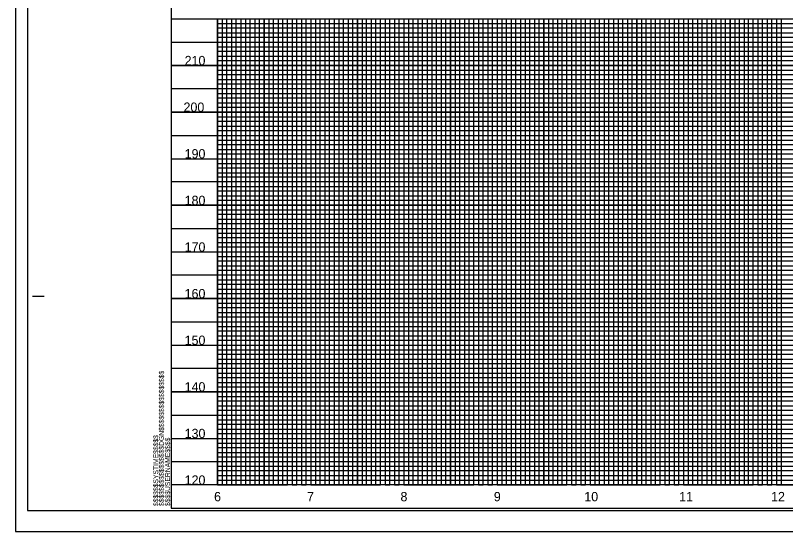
# Model space of a CAD drawing. Extents: x 1779926 to 1781610, y 620464 to 621564.
# Drawn here: x 1779926 to 1780753, y 620464 to 621018 of the extents above; entities that cross this region are included whole.
import ezdxf

# ---------------------------------------------------------------- set-up
doc = ezdxf.new("R2010")
doc.units = 0
for name, color, linetype in [('Exist Vertical Profile Horizontal Axis Label Major', 7, 'Continuous'), ('Exist Vertical Profile Vertical Axis Label', 7, 'Continuous'), ('Scratch_Level_0', 7, 'Continuous'), ('Sheet Cutting Line CELL', 7, 'Continuous'), ('Sheet DOT Grid CELL', 7, 'Continuous'), ('Sheet Layout Profile Border Port 2', 7, 'Continuous'), ('Sheet Plot Border Inside CELL', 7, 'Continuous'), ('Sheet Plot Border Outside CELL', 7, 'Continuous'), ('Sheet Profile CELL', 7, 'Continuous'), ('Sheet Profile Grid Major CELL', 7, 'Continuous'), ('Sheet Profile Grid Middle CELL', 7, 'Continuous'), ('Sheet Profile Grid Minor CELL', 7, 'Continuous')]:
    doc.layers.add(name, color=color, linetype=linetype)

msp = doc.modelspace()

# ---------------------------------------------------------------- linework, layer by layer
at = {"layer": 'Scratch_Level_0'}
msp.add_lwpolyline([(1780142.96, 620514.19), (1780142.96, 621014.19), (1781542.96, 621014.19), (1781542.96, 620514.19)], close=True, dxfattribs=at)
at = {"layer": 'Sheet Cutting Line CELL'}
for p, q in [((1779925.96, 621564.19), (1779925.96, 620464.19)), ((1779925.96, 620464.19), (1781609.96, 620464.19))]:
    msp.add_line(p, q, dxfattribs=at)
at = {"layer": 'Sheet DOT Grid CELL'}
for p, q in [((1780092.96, 621014.19), (1781592.85, 621014.19)), ((1780142.96, 621014.19), (1780142.96, 620514.19)), ((1780192.96, 621014.19), (1780192.96, 620514.19)), ((1780242.96, 621014.19), (1780242.96, 620514.19)), ((1780292.96, 621014.19), (1780292.96, 620514.19)), ((1780342.96, 621014.19), (1780342.96, 620514.19)), ((1780392.96, 621014.19), (1780392.96, 620514.19)), ((1780442.96, 621014.19), (1780442.96, 620514.19)), ((1780492.96, 621014.19), (1780492.96, 620514.19)), ((1780542.96, 621014.19), (1780542.96, 620514.19)), ((1780592.96, 621014.19), (1780592.96, 620514.19)), ((1780642.96, 621014.19), (1780642.96, 620514.19)), ((1780692.96, 621014.19), (1780692.96, 620514.19)), ((1780742.96, 621014.19), (1780742.96, 620514.19)), ((1780092.96, 620964.19), (1781592.85, 620964.19)), ((1780092.96, 620914.19), (1781592.85, 620914.19)), ((1780092.96, 620864.19), (1781592.85, 620864.19)), ((1780092.96, 620814.19), (1781592.85, 620814.19)), ((1780092.96, 620764.19), (1781592.85, 620764.19)), ((1780092.96, 620714.19), (1781592.85, 620714.19)), ((1780092.96, 620664.19), (1781592.85, 620664.19)), ((1780092.96, 620614.19), (1781592.85, 620614.19)), ((1780092.96, 620564.19), (1781592.85, 620564.19))]:
    msp.add_line(p, q, dxfattribs=at)
at = {"layer": 'Sheet Layout Profile Border Port 2'}
for points in [[(1780142.96, 621014.19), (1781542.96, 621014.19), (1781542.96, 620514.19), (1780142.96, 620514.19)], [(1780142.96, 621014.19), (1781382.96, 621014.19), (1781382.96, 620514.19), (1780142.96, 620514.19)]]:
    msp.add_lwpolyline(points, close=True, dxfattribs=at)
at = {"layer": 'Sheet Plot Border Inside CELL'}
msp.add_lwpolyline([(1779938.96, 620486.64), (1781605.46, 620486.64), (1781605.46, 621541.74), (1779938.96, 621541.74)], close=True, dxfattribs=at)
at = {"layer": 'Sheet Plot Border Outside CELL'}
msp.add_lwpolyline([(1779925.96, 620464.19), (1781609.96, 620464.19), (1781609.96, 621564.19), (1779925.96, 621564.19)], close=True, dxfattribs=at)
at = {"layer": 'Sheet Profile CELL'}
for p, q in [((1780092.96, 621014.19), (1781592.96, 621014.19)), ((1779944.46, 620716.69), (1779956.96, 620716.69)), ((1781592.96, 620514.19), (1780092.96, 620514.19)), ((1780092.96, 620489.19), (1781592.96, 620489.19)), ((1780092.96, 620489.19), (1780092.96, 620489.19)), ((1780092.96, 620489.19), (1780092.96, 620489.19)), ((1780092.96, 620489.19), (1780092.96, 620489.19)), ((1780092.96, 620489.19), (1780092.96, 620489.19)), ((1780092.96, 620489.19), (1780092.96, 620489.19)), ((1780092.96, 620489.19), (1780092.96, 620489.19)), ((1780092.96, 620489.19), (1780092.96, 620489.19))]:
    msp.add_line(p, q, dxfattribs=at)
msp.add_lwpolyline([(1781592.96, 621539.19), (1780092.96, 621539.19), (1780092.96, 620489.19), (1781592.96, 620489.19)], close=True, dxfattribs=at)
msp.add_lwpolyline([(1780130.46, 620489.19), (1780130.46, 620489.19)], dxfattribs=at)
at = {"layer": 'Sheet Profile Grid Major CELL'}
for p, q in [((1780592.96, 621014.19), (1780642.96, 621014.19)), ((1780692.96, 621014.19), (1780742.96, 621014.19)), ((1780092.96, 620514.19), (1780092.96, 620514.19))]:
    msp.add_line(p, q, dxfattribs=at)
for points in [[(1780142.96, 621014.19), (1780142.96, 620514.19), (1780192.96, 620514.19), (1780192.96, 621014.19), (1780242.96, 621014.19), (1780242.96, 620514.19), (1780292.96, 620514.19), (1780292.96, 621014.19), (1780342.96, 621014.19), (1780342.96, 620514.19), (1780392.96, 620514.19), (1780392.96, 621014.19), (1780442.96, 621014.19), (1780442.96, 620514.19), (1780492.96, 620514.19), (1780492.96, 621014.19), (1780542.96, 621014.19), (1780542.96, 620514.19), (1780592.96, 620514.19), (1780592.96, 621014.19), (1780642.96, 621014.19), (1780642.96, 620514.19), (1780692.96, 620514.19), (1780692.96, 621014.19), (1780742.96, 621014.19), (1780742.96, 620514.19), (1780792.96, 620514.19)], [(1781592.96, 620964.19), (1780092.96, 620964.19)], [(1781592.96, 620914.19), (1780092.96, 620914.19), (1780092.96, 620864.19), (1781592.96, 620864.19)], [(1781592.96, 620814.19), (1780092.96, 620814.19), (1780092.96, 620764.19), (1781592.96, 620764.19)], [(1781592.96, 620714.19), (1780092.96, 620714.19), (1780092.96, 620664.19), (1781592.96, 620664.19)], [(1781592.96, 620614.19), (1780092.96, 620614.19), (1780092.96, 620614.19), (1780092.96, 620564.19), (1781592.96, 620564.19)], [(1781592.96, 620514.19), (1780092.96, 620514.19)]]:
    msp.add_lwpolyline(points, dxfattribs=at)
at = {"layer": 'Sheet Profile Grid Middle CELL'}
for points in [[(1780117.96, 621014.19), (1780167.96, 621014.19), (1780167.96, 620514.19), (1780217.96, 620514.19), (1780217.96, 621014.19), (1780267.96, 621014.19), (1780267.96, 620514.19), (1780317.96, 620514.19), (1780317.96, 621014.19), (1780367.96, 621014.19), (1780367.96, 620514.19), (1780417.96, 620514.19), (1780417.96, 621014.19), (1780467.96, 621014.19), (1780467.96, 620514.19), (1780517.96, 620514.19), (1780517.96, 621014.19), (1780567.96, 621014.19), (1780567.96, 620514.19), (1780617.96, 620514.19), (1780617.96, 621014.19), (1780667.96, 621014.19), (1780667.96, 620514.19), (1780717.96, 620514.19), (1780717.96, 620514.19), (1780717.96, 621014.19), (1780767.96, 621014.19)], [(1780092.96, 620989.19), (1781592.96, 620989.19)], [(1781592.96, 620939.19), (1780092.96, 620939.19), (1780092.96, 620889.19), (1781592.96, 620889.19)], [(1781592.96, 620839.19), (1780092.96, 620839.19), (1780092.96, 620789.19), (1781592.96, 620789.19)], [(1781592.96, 620739.19), (1780092.96, 620739.19), (1780092.96, 620689.19), (1781592.96, 620689.19)], [(1781592.96, 620639.19), (1780092.96, 620639.19), (1780092.96, 620589.19), (1781592.96, 620589.19)], [(1781592.96, 620539.19), (1780092.96, 620539.19)]]:
    msp.add_lwpolyline(points, dxfattribs=at)
at = {"layer": 'Sheet Profile Grid Minor CELL'}
for p, q in [((1780142.96, 621009.19), (1781542.96, 621009.19)), ((1781542.96, 621004.19), (1780142.96, 621004.19)), ((1780142.96, 620999.19), (1781542.96, 620999.19)), ((1781542.96, 620994.19), (1780142.96, 620994.19)), ((1780142.96, 620984.19), (1781542.96, 620984.19)), ((1781542.96, 620979.19), (1780142.96, 620979.19)), ((1780142.96, 620974.19), (1781542.96, 620974.19)), ((1781542.96, 620969.19), (1780142.96, 620969.19)), ((1780142.96, 620959.19), (1781542.96, 620959.19)), ((1781542.96, 620954.19), (1780142.96, 620954.19)), ((1780142.96, 620949.19), (1781542.96, 620949.19)), ((1781542.96, 620944.19), (1780142.96, 620944.19)), ((1780142.96, 620934.19), (1781542.96, 620934.19)), ((1781542.96, 620929.19), (1780142.96, 620929.19)), ((1780142.96, 620924.19), (1781542.96, 620924.19)), ((1781542.96, 620919.19), (1780142.96, 620919.19)), ((1780142.96, 620909.19), (1781542.96, 620909.19)), ((1781542.96, 620904.19), (1780142.96, 620904.19)), ((1780142.96, 620899.19), (1781542.96, 620899.19)), ((1781542.96, 620894.19), (1780142.96, 620894.19)), ((1780142.96, 620884.19), (1781542.96, 620884.19)), ((1781542.96, 620879.19), (1780142.96, 620879.19)), ((1780142.96, 620874.19), (1781542.96, 620874.19)), ((1781542.96, 620869.19), (1780142.96, 620869.19)), ((1780142.96, 620859.19), (1781542.96, 620859.19)), ((1781542.96, 620854.19), (1780142.96, 620854.19)), ((1780142.96, 620849.19), (1781542.96, 620849.19)), ((1781542.96, 620844.19), (1780142.96, 620844.19)), ((1780142.96, 620834.19), (1781542.96, 620834.19)), ((1781542.96, 620829.19), (1780142.96, 620829.19)), ((1780142.96, 620824.19), (1781542.96, 620824.19)), ((1781542.96, 620819.19), (1780142.96, 620819.34)), ((1780142.96, 620809.19), (1781542.96, 620809.19)), ((1781542.96, 620804.19), (1780142.96, 620804.19)), ((1780142.96, 620799.19), (1781542.96, 620799.19)), ((1781542.96, 620794.19), (1780142.96, 620794.19)), ((1780142.96, 620784.19), (1781542.96, 620784.19)), ((1781542.96, 620779.19), (1780142.96, 620779.19)), ((1780142.96, 620774.19), (1781542.96, 620774.19)), ((1781542.96, 620769.19), (1780142.96, 620769.19)), ((1780142.96, 620759.19), (1781542.96, 620759.19)), ((1781542.96, 620754.19), (1780142.96, 620754.19)), ((1780142.96, 620749.19), (1781542.96, 620749.19)), ((1781542.96, 620744.19), (1780142.96, 620744.19)), ((1780142.96, 620734.19), (1781542.96, 620734.19)), ((1781542.96, 620729.19), (1780142.96, 620729.19)), ((1780142.96, 620724.19), (1781542.96, 620724.19)), ((1781542.96, 620719.19), (1780142.96, 620719.19)), ((1780142.96, 620709.19), (1781542.96, 620709.19)), ((1781542.96, 620704.19), (1780142.96, 620704.19)), ((1780142.96, 620699.19), (1781542.96, 620699.19)), ((1781542.96, 620694.19), (1780142.96, 620694.19)), ((1780142.96, 620684.19), (1781542.96, 620684.19)), ((1781542.96, 620679.19), (1780142.96, 620679.19)), ((1780142.96, 620674.19), (1781542.96, 620674.19)), ((1781542.96, 620669.19), (1780142.96, 620669.19)), ((1780142.96, 620659.19), (1781542.96, 620659.19)), ((1781542.96, 620654.19), (1780142.96, 620654.19)), ((1780142.96, 620649.19), (1781542.96, 620649.19)), ((1781542.96, 620644.19), (1780142.96, 620644.19)), ((1780142.96, 620634.19), (1781542.96, 620634.19)), ((1781542.96, 620629.19), (1780142.96, 620629.19)), ((1780142.96, 620624.19), (1781542.96, 620624.19)), ((1781542.96, 620619.19), (1780142.96, 620619.19)), ((1780142.96, 620609.19), (1781542.96, 620609.19)), ((1781542.96, 620604.19), (1780142.96, 620604.19)), ((1780142.96, 620599.19), (1781542.96, 620599.19)), ((1781542.96, 620594.19), (1780142.96, 620594.19)), ((1780142.96, 620584.19), (1781542.96, 620584.19)), ((1781542.96, 620579.19), (1780142.96, 620579.19)), ((1780142.96, 620574.19), (1781542.96, 620574.19)), ((1781542.96, 620569.19), (1780142.96, 620569.19)), ((1780142.96, 620559.19), (1781542.96, 620559.19)), ((1781542.96, 620554.19), (1780142.96, 620554.19)), ((1780142.96, 620549.19), (1781542.96, 620549.19)), ((1781542.96, 620544.19), (1780142.96, 620544.19)), ((1780142.96, 620534.19), (1781542.96, 620534.19)), ((1781542.96, 620529.19), (1780142.96, 620529.19)), ((1780142.96, 620524.19), (1781542.96, 620524.19)), ((1780142.96, 620519.19), (1781542.96, 620519.19))]:
    msp.add_line(p, q, dxfattribs=at)
for points in [[(1780142.96, 621014.19), (1780147.96, 621014.19), (1780147.96, 620514.19), (1780152.96, 620514.19), (1780152.96, 621014.19), (1780157.96, 621014.19), (1780157.96, 620514.19), (1780162.96, 620514.19), (1780162.96, 621014.19), (1780172.96, 621014.19), (1780172.96, 620514.19), (1780177.96, 620514.19), (1780177.96, 621014.19), (1780182.96, 621014.19), (1780182.96, 620514.19), (1780187.96, 620514.19), (1780197.96, 620514.19), (1780202.96, 620514.19), (1780202.96, 621014.19), (1780207.96, 621014.19), (1780207.96, 620514.19), (1780212.96, 620514.19), (1780212.96, 621014.19), (1780222.96, 621014.19), (1780222.96, 620514.19), (1780227.96, 620514.19), (1780227.96, 621014.19), (1780232.96, 621014.19), (1780232.96, 620514.19), (1780237.96, 620514.19), (1780237.96, 621014.19), (1780247.96, 621014.19), (1780247.96, 620514.19), (1780252.96, 620514.19), (1780252.96, 621014.19), (1780257.96, 621014.19), (1780257.96, 620514.19), (1780262.96, 620514.19), (1780262.96, 621014.19), (1780272.96, 621014.19), (1780272.96, 620514.19), (1780277.96, 620514.19), (1780277.96, 621014.19), (1780282.96, 621014.19), (1780282.96, 620514.19), (1780287.96, 620514.19), (1780287.96, 621014.19), (1780297.96, 621014.19), (1780297.96, 620514.19), (1780302.96, 620514.19), (1780302.96, 621014.19), (1780307.96, 621014.19), (1780307.96, 620514.19), (1780312.96, 620514.19), (1780312.96, 621014.19), (1780322.96, 621014.19), (1780322.96, 620514.19), (1780327.96, 620514.19), (1780327.96, 621014.19), (1780332.96, 621014.19), (1780332.96, 620514.19), (1780337.96, 620514.19), (1780337.96, 621014.19), (1780347.96, 621014.19), (1780347.96, 620514.19), (1780352.96, 620514.19), (1780352.96, 621014.19), (1780357.96, 621014.19), (1780357.96, 620514.19)], [(1780187.96, 620514.19), (1780187.96, 621014.19), (1780197.96, 621014.19), (1780197.96, 620514.19)], [(1780357.96, 620514.19), (1780362.96, 620514.19), (1780362.96, 621014.19), (1780372.96, 621014.19), (1780372.96, 620514.19), (1780377.96, 620514.19), (1780377.96, 621014.19), (1780382.96, 621014.19), (1780382.96, 620514.19), (1780387.96, 620514.19), (1780387.96, 621014.19), (1780397.96, 621014.19), (1780397.96, 620514.19), (1780402.96, 620514.19), (1780402.96, 621014.19), (1780407.96, 621014.19), (1780407.96, 620514.19), (1780412.96, 620514.19), (1780412.96, 621014.19), (1780422.96, 621014.19), (1780422.96, 620514.19), (1780427.96, 620514.19), (1780427.96, 621014.19), (1780432.96, 621014.19), (1780432.96, 620514.19), (1780437.96, 620514.19), (1780437.96, 621014.19), (1780447.96, 621014.19), (1780447.96, 620514.19), (1780452.96, 620514.19), (1780452.96, 621014.19), (1780457.96, 621014.19), (1780457.96, 620514.19), (1780462.96, 620514.19), (1780462.96, 621014.19), (1780472.96, 621014.19), (1780472.96, 620514.19), (1780477.96, 620514.19), (1780477.96, 621014.19), (1780482.96, 621014.19), (1780482.96, 620514.19), (1780487.96, 620514.19), (1780487.96, 621014.19), (1780497.96, 621014.19), (1780497.96, 620514.19), (1780502.96, 620514.19), (1780502.96, 621014.19), (1780507.96, 621014.19), (1780507.96, 620514.19), (1780512.96, 620514.19), (1780512.96, 621014.19), (1780522.96, 621014.19), (1780522.96, 620514.19), (1780527.96, 620514.19), (1780527.96, 621014.19), (1780532.96, 621014.19), (1780532.96, 620514.19), (1780537.96, 620514.19), (1780537.96, 621014.19), (1780547.96, 621014.19), (1780547.96, 620514.19), (1780552.96, 620514.19), (1780552.96, 621014.19), (1780557.96, 621014.19), (1780557.96, 620514.19), (1780562.96, 620514.19), (1780562.96, 621014.19), (1780572.96, 621014.19), (1780572.96, 620514.19), (1780577.96, 620514.19), (1780577.96, 621014.19), (1780582.96, 621014.19), (1780582.96, 620514.19), (1780587.96, 620514.19), (1780587.96, 621014.19), (1780597.96, 621014.19), (1780597.96, 620514.19), (1780602.96, 620514.19), (1780602.96, 621014.19), (1780607.96, 621014.19), (1780607.96, 620514.19), (1780612.96, 620514.19), (1780612.96, 621014.19), (1780622.96, 621014.19), (1780622.96, 620514.19), (1780627.96, 620514.19), (1780627.96, 621014.19), (1780632.96, 621014.19), (1780632.96, 620514.19), (1780637.96, 620514.19), (1780637.96, 621014.19), (1780647.96, 621014.19), (1780647.96, 620514.19), (1780652.96, 620514.19), (1780652.96, 621014.19), (1780657.96, 621014.19), (1780657.96, 620514.19), (1780662.96, 620514.19), (1780662.96, 621014.19), (1780672.96, 621014.19)], [(1780672.96, 621014.19), (1780672.96, 620514.19), (1780677.96, 620514.19), (1780677.96, 621014.19), (1780682.96, 621014.19), (1780682.96, 620514.19), (1780687.96, 620514.19), (1780687.96, 621014.19), (1780697.96, 621014.19), (1780697.96, 620514.19), (1780702.96, 620514.19), (1780702.96, 621014.19), (1780707.96, 621014.19), (1780707.96, 620514.19), (1780712.96, 620514.19), (1780712.96, 621014.19), (1780722.96, 621014.19), (1780722.96, 620514.19), (1780727.96, 620514.19), (1780727.96, 621014.19), (1780732.96, 621014.19), (1780732.96, 620514.19), (1780737.96, 620514.19), (1780737.96, 621014.19), (1780747.96, 621014.19), (1780747.96, 620514.19), (1780752.96, 620514.19)]]:
    msp.add_lwpolyline(points, dxfattribs=at)

# ---------------------------------------------------------------- texts
at = {"layer": 'Exist Vertical Profile Horizontal Axis Label Major'}
for s, p in [('6', (1780139.19, 620496.69)), ('7', (1780238.94, 620496.69)), ('8', (1780339.27, 620496.69)), ('9', (1780439.45, 620496.69)), ('10', (1780536.55, 620496.69)), ('11', (1780638.31, 620496.69)), ('12', (1780737.04, 620496.69))]:
    msp.add_text(s, height=10, dxfattribs=at).set_placement(p)
at = {"layer": 'Exist Vertical Profile Vertical Axis Label'}
for s, p in [('210', (1780107.59, 620964.44)), ('200', (1780106.39, 620914.44)), ('190', (1780107.59, 620864.44)), ('180', (1780107.59, 620814.44)), ('170', (1780107.59, 620764.44)), ('160', (1780107.59, 620714.44)), ('150', (1780107.59, 620664.44)), ('140', (1780107.59, 620614.44)), ('130', (1780107.59, 620564.44)), ('120', (1780107.59, 620514.44))]:
    msp.add_text(s, height=10, dxfattribs=at).set_placement(p)
at = {"layer": 'Sheet Profile CELL'}
for s, p in [('$$$$$$$$$$$$$$$$DGN$$$$$$$$$$$$$$$$', (1780085.32, 620491.57)), ('$$$$$$SYSTIME$$$$$', (1780079.27, 620491.57)), ('$$$$USERNAME$$$$', (1780091.9, 620491.58))]:
    msp.add_text(s, height=5.25, rotation=90, dxfattribs=at).set_placement(p)

doc.saveas('drawing.dxf')
